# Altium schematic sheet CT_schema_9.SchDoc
size 274 x 160 mm
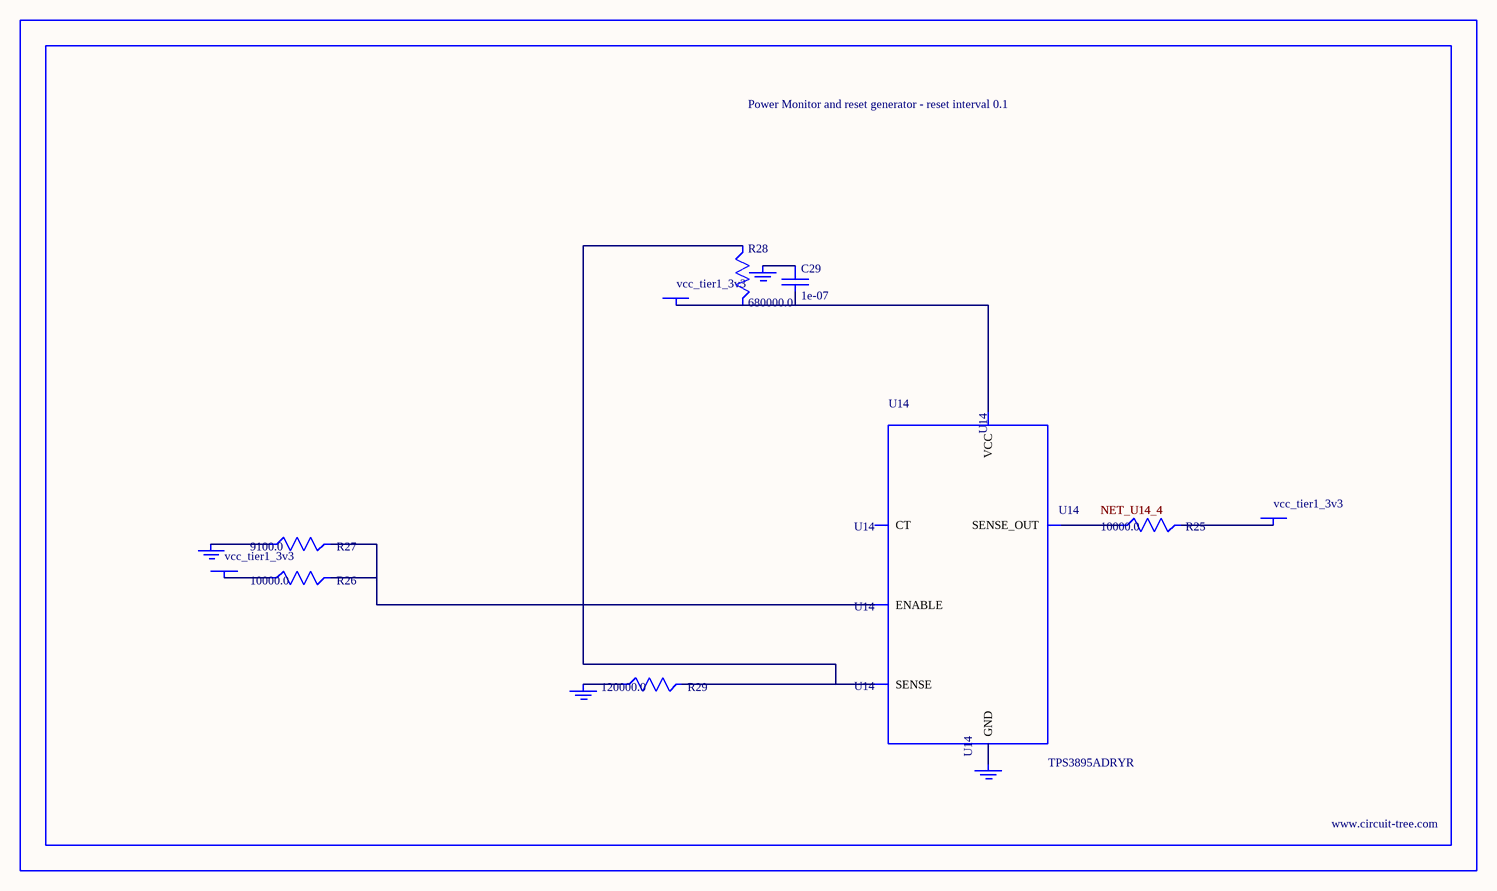
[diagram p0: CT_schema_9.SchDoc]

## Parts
BORDER8  (no value)
C29  1e-07  [C0402]
GND_INSTANCE_8_0  (no value)
GND_INSTANCE_8_1  (no value)
GND_INSTANCE_8_2  (no value)
GND_INSTANCE_8_3  (no value)
POWER_INSTANCE_8_0  vcc_tier1_3v3
POWER_INSTANCE_8_1  vcc_tier1_3v3
POWER_INSTANCE_8_2  vcc_tier1_3v3
R25  10000.0  [R0603]
R26  10000.0  [R0603]
R27  9100.0  [R0603]
R28  680000.0  [R0603]
R29  120000.0  [R0603]
U14  TPS3895ADRYR  [SON-6]

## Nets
NetC29_1: C29.1 GND_INSTANCE_8_2.0(GND)
NetC29_2: C29.2 POWER_INSTANCE_8_2.0(PWR) R28.2 U14.6(VCC)
NetGND_INSTANCE_8_0_0: GND_INSTANCE_8_0.0(GND) R27.1
NetGND_INSTANCE_8_1_0: GND_INSTANCE_8_1.0(GND) R29.1
NetGND_INSTANCE_8_3_0: GND_INSTANCE_8_3.0(GND) U14.2(GND)
NetPOWER_INSTANCE_8_0_0: POWER_INSTANCE_8_0.0(PWR) R26.1
NetPOWER_INSTANCE_8_1_0: POWER_INSTANCE_8_1.0(PWR) R25.2
NetR25_1: R25.1 U14.4(SENSE_OUT)
NetR26_2: R26.2 R27.2 U14.1(ENABLE)
NetR28_1: R28.1 R29.2 U14.3(SENSE)

Not connected (* = marked no-connect by the designer): U14 5(CT)

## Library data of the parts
BORDER8 = BORDER_PAGE8
C29 = C0402C104K3RACTU
GND_INSTANCE_8_0-GND_INSTANCE_8_3 = GND
POWER_INSTANCE_8_0-POWER_INSTANCE_8_2 = PWR
R25 R26 = RC0603JR-0710KL
R27 = RC0603JR-079K1L
R28 = RC0603JR-07680KL
R29 = RC0603JR-07120KL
